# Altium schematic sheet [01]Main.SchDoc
size A4; SheetNumber: 1; SheetTotal: 5
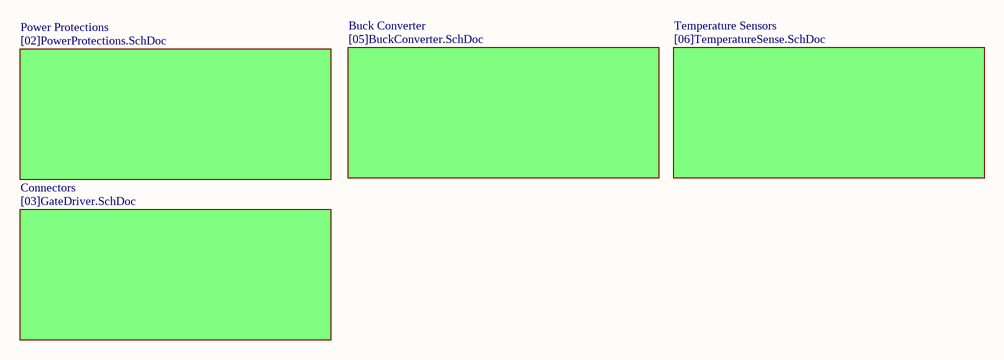
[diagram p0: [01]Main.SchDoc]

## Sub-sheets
Buck Converter = [05]BuckConverter.SchDoc: no entries
Connectors = [03]GateDriver.SchDoc: no entries
Power Protections = [02]PowerProtections.SchDoc: no entries
Temperature Sensors = [06]TemperatureSense.SchDoc: no entries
